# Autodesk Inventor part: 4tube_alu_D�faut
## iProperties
Created: 2011-01
Part Number: 4tube_alu_D�faut
Document SubType Name: Modeling
Designer: eric
Density: 1 g/cm^3
Mass: 88.0744 g
Surface Area: 888.505 cm^2
Volume: 88.0744 cm^3
Author: eric
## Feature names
1. Base1
